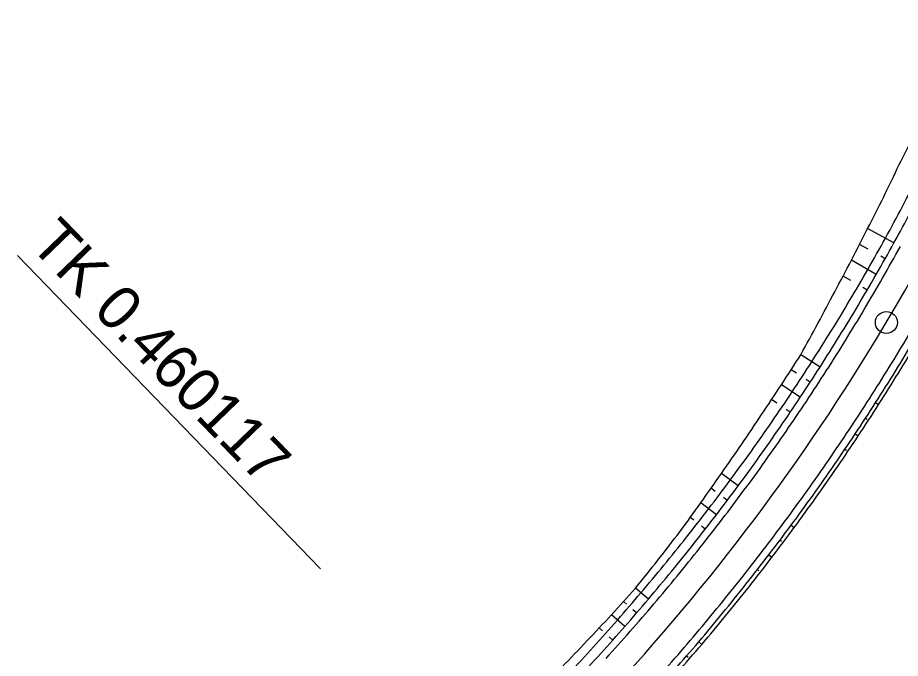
# Model space of a CAD drawing. Extents: x -481656 to -478728, y -1113199 to -1110710.
# Drawn here: x -480282.1 to -480222, y -1112650.6 to -1112606.9 of the extents above; entities that cross this region are included whole.
import ezdxf

# ---------------------------------------------------------------- set-up
doc = ezdxf.new("R2010")
doc.units = 0
for name, color, linetype in [('C14_HATCH_SLOPE_L', 7, 'Continuous'), ('C14_HATCH_SLOPE_R', 7, 'Continuous'), ('C14_HECTOMETRY', 7, 'Continuous'), ('C14_HLBODY', 7, 'Continuous'), ('C14_HRANA_TELESO', 7, 'Continuous'), ('C14_KORUNA', 7, 'Continuous'), ('C14_OSA', 7, 'Continuous'), ('C14_PRIKOP', 7, 'Continuous'), ('C14_VOZOVKA', 7, 'Continuous'), ('C14_ZPEVKRAJ', 7, 'Continuous')]:
    doc.layers.add(name, color=color, linetype=linetype)

msp = doc.modelspace()

# ---------------------------------------------------------------- linework, layer by layer
at = {"layer": 'C14_HATCH_SLOPE_L'}
for p, q in [((-480222.403, -1112622.309), (-480224.194, -1112621.323)), ((-480222.403, -1112622.309), (-480224.194, -1112621.323)), ((-480224.162, -1112622.733), (-480224.742, -1112622.408)), ((-480224.162, -1112622.733), (-480224.742, -1112622.408)), ((-480223.609, -1112624.456), (-480225.299, -1112623.488)), ((-480223.609, -1112624.456), (-480225.299, -1112623.488)), ((-480223.002, -1112623.385), (-480223.292, -1112623.222)), ((-480223.002, -1112623.385), (-480223.292, -1112623.222)), ((-480225.333, -1112624.875), (-480225.866, -1112624.564)), ((-480225.333, -1112624.875), (-480225.866, -1112624.564)), ((-480224.225, -1112625.522), (-480224.513, -1112625.354)), ((-480224.225, -1112625.522), (-480224.513, -1112625.354)), ((-480227.439, -1112630.772), (-480228.752, -1112629.93)), ((-480227.439, -1112630.772), (-480228.752, -1112629.93)), ((-480229.036, -1112631.2), (-480229.407, -1112630.957)), ((-480229.036, -1112631.2), (-480229.407, -1112630.957)), ((-480228.785, -1112632.834), (-480230.071, -1112631.979)), ((-480228.785, -1112632.834), (-480230.071, -1112631.979)), ((-480228.107, -1112631.806), (-480228.386, -1112631.624)), ((-480228.107, -1112631.806), (-480228.386, -1112631.624)), ((-480230.382, -1112633.239), (-480230.743, -1112632.995)), ((-480230.382, -1112633.239), (-480230.743, -1112632.995)), ((-480229.471, -1112633.857), (-480229.746, -1112633.67)), ((-480229.471, -1112633.857), (-480229.746, -1112633.67)), ((-480233.026, -1112638.882), (-480234.162, -1112638.042)), ((-480233.026, -1112638.882), (-480234.162, -1112638.042)), ((-480234.578, -1112639.256), (-480234.86, -1112639.043)), ((-480234.578, -1112639.256), (-480234.86, -1112639.043)), ((-480233.763, -1112639.869), (-480234.029, -1112639.668)), ((-480233.763, -1112639.869), (-480234.029, -1112639.668)), ((-480234.507, -1112640.849), (-480235.567, -1112640.038)), ((-480234.507, -1112640.849), (-480235.567, -1112640.038)), ((-480236.034, -1112641.222), (-480236.282, -1112641.028)), ((-480236.034, -1112641.222), (-480236.282, -1112641.028)), ((-480235.259, -1112641.824), (-480235.522, -1112641.62)), ((-480239.142, -1112646.601), (-480240.019, -1112645.858)), ((-480240.642, -1112646.934), (-480240.836, -1112646.766)), ((-480240.75, -1112648.466), (-480241.66, -1112647.668)), ((-480239.942, -1112647.537), (-480240.194, -1112647.319)), ((-480242.278, -1112648.753), (-480242.492, -1112648.562)), ((-480241.566, -1112649.388), (-480241.814, -1112649.166))]:
    msp.add_line(p, q, dxfattribs=at)
at = {"layer": 'C14_HATCH_SLOPE_R'}
for p, q in [((-480223.65, -1112633.201), (-480223.445, -1112633.332)), ((-480224.339, -1112634.266), (-480224.236, -1112634.334)), ((-480224.133, -1112634.401), (-480224.133, -1112634.401)), ((-480225.037, -1112635.325), (-480224.83, -1112635.463)), ((-480225.744, -1112636.379), (-480225.64, -1112636.45)), ((-480225.536, -1112636.52), (-480225.536, -1112636.52)), ((-480229.408, -1112641.557), (-480229.198, -1112641.713)), ((-480230.167, -1112642.574), (-480230.062, -1112642.654)), ((-480229.956, -1112642.733), (-480229.956, -1112642.733)), ((-480230.934, -1112643.585), (-480230.722, -1112643.747)), ((-480231.709, -1112644.589), (-480231.603, -1112644.672)), ((-480231.497, -1112644.754), (-480231.497, -1112644.754)), ((-480235.71, -1112649.511), (-480235.503, -1112649.687)), ((-480236.535, -1112650.476), (-480236.434, -1112650.563))]:
    msp.add_line(p, q, dxfattribs=at)
at = {"layer": 'C14_HECTOMETRY'}
msp.add_circle((-480222.917, -1112627.733), 0.75, dxfattribs=at)
at = {"layer": 'C14_HLBODY'}
msp.add_line((-480282.134, -1112623.171), (-480261.496, -1112644.529), dxfattribs=at)
at = {"layer": 'C14_HRANA_TELESO'}
for centre, radius, start, end in [((-480249.238, -1112602.443), 30.829, 331.89249, 340.92151), ((-480353.71, -1112554.722), 145.637, 332.78643, 334.69706), ((-480354.6, -1112556.11), 145.803, 331.52018, 333.43154), ((-480354.6, -1112556.11), 145.803, 331.52018, 333.43154), ((-480356.184, -1112558.586), 146.044, 330.75701, 332.67027), ((-480356.184, -1112558.586), 146.044, 330.75701, 332.67027), ((-480351.985, -1112551.294), 152.489, 327.45257, 329.36243), ((-480352.342, -1112551.818), 146.205, 325.79599, 327.70589), ((-480352.342, -1112551.818), 146.205, 325.79599, 327.70589), ((-480351.973, -1112551.258), 152.498, 325.52898, 327.43884), ((-480353.833, -1112553.921), 146.279, 324.89521, 326.80561), ((-480353.833, -1112553.921), 146.279, 324.89521, 326.80561), ((-480354.596, -1112554.777), 146.415, 323.42998, 325.3408), ((-480354.596, -1112554.777), 146.415, 323.42998, 325.3408), ((-480351.983, -1112551.257), 152.507, 323.62093, 325.5308), ((-480353.853, -1112553.567), 146.547, 320.96691, 322.87723), ((-480351.996, -1112551.259), 152.516, 321.71453, 323.62439), ((-480349.386, -1112548.325), 146.54, 316.36324, 318.2737), ((-480351.841, -1112551.056), 152.521, 319.70878, 321.61864), ((-480350.222, -1112549.354), 146.44, 314.97023, 316.88033), ((-480351.479, -1112550.643), 152.512, 317.5927, 319.50257)]:
    msp.add_arc(centre, radius, start, end, dxfattribs=at)
at = {"layer": 'C14_KORUNA'}
for radius, start, end in [(147.75, 331.16085, 333.07071), (147.75, 329.25099, 331.16085), (147.75, 327.34113, 329.25099), (152.25, 327.34113, 329.25099), (147.75, 325.43127, 327.34113), (152.25, 325.43127, 327.34113), (147.75, 323.52141, 325.43127), (152.25, 323.52141, 325.43127), (147.75, 321.61155, 323.52141), (152.25, 321.61156, 323.52141), (147.75, 319.70169, 321.61155), (152.25, 319.70169, 321.61155), (147.75, 317.79183, 319.70169), (152.25, 317.79184, 319.70169), (147.75, 315.88197, 317.79183)]:
    msp.add_arc((-480351.829, -1112551.041), radius, start, end, dxfattribs=at)
at = {"layer": 'C14_OSA'}
msp.add_arc((-480351.829, -1112551.041), 150, 314.01664, 338.11863, dxfattribs=at)
at = {"layer": 'C14_PRIKOP'}
for start, end in [(331.16085, 333.07071), (329.25099, 331.16085), (329.25099, 331.16085), (327.34113, 329.25099), (327.34113, 329.25099), (325.43127, 327.34113), (325.43127, 327.34113), (323.52141, 325.43127), (323.52141, 325.43127), (321.61155, 323.52141), (321.61155, 323.52141), (319.70169, 321.61155), (317.79183, 319.70169), (315.88197, 317.79183)]:
    msp.add_arc((-480351.829, -1112551.041), 147.084, start, end, dxfattribs=at)
at = {"layer": 'C14_VOZOVKA'}
for radius, start, end in [(148.25, 329.25099, 331.16085), (148.25, 327.34113, 329.25099), (151.75, 327.34113, 329.25099), (148.25, 325.43127, 327.34113), (151.75, 325.43127, 327.34113), (148.25, 323.52141, 325.43127), (151.75, 323.52141, 325.43127), (148.25, 321.61155, 323.52141), (151.75, 321.61155, 323.52141), (148.25, 319.70169, 321.61155), (151.75, 319.70169, 321.61155), (148.25, 317.79183, 319.70169), (151.75, 317.79183, 319.70169)]:
    msp.add_arc((-480351.829, -1112551.041), radius, start, end, dxfattribs=at)
at = {"layer": 'C14_ZPEVKRAJ'}
for radius, start, end in [(148.25, 329.25099, 331.16085), (148.25, 327.34113, 329.25099), (151.75, 327.34113, 329.25099), (148.25, 325.43127, 327.34113), (151.75, 325.43127, 327.34113), (148.25, 323.52141, 325.43127), (151.75, 323.52141, 325.43127), (148.25, 321.61155, 323.52141), (151.75, 321.61155, 323.52141), (148.25, 319.70169, 321.61155), (151.75, 319.70169, 321.61155), (148.25, 317.79183, 319.70169), (151.75, 317.79183, 319.70169)]:
    msp.add_arc((-480351.829, -1112551.041), radius, start, end, dxfattribs=at)

# ---------------------------------------------------------------- texts
at = {"layer": 'C14_HLBODY'}
msp.add_text('TK 0.460117', height=3, rotation=314.01664, dxfattribs=at).set_placement((-480281.415, -1112622.475))

doc.saveas('drawing.dxf')
